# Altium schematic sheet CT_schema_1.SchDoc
size 707 x 532 mm
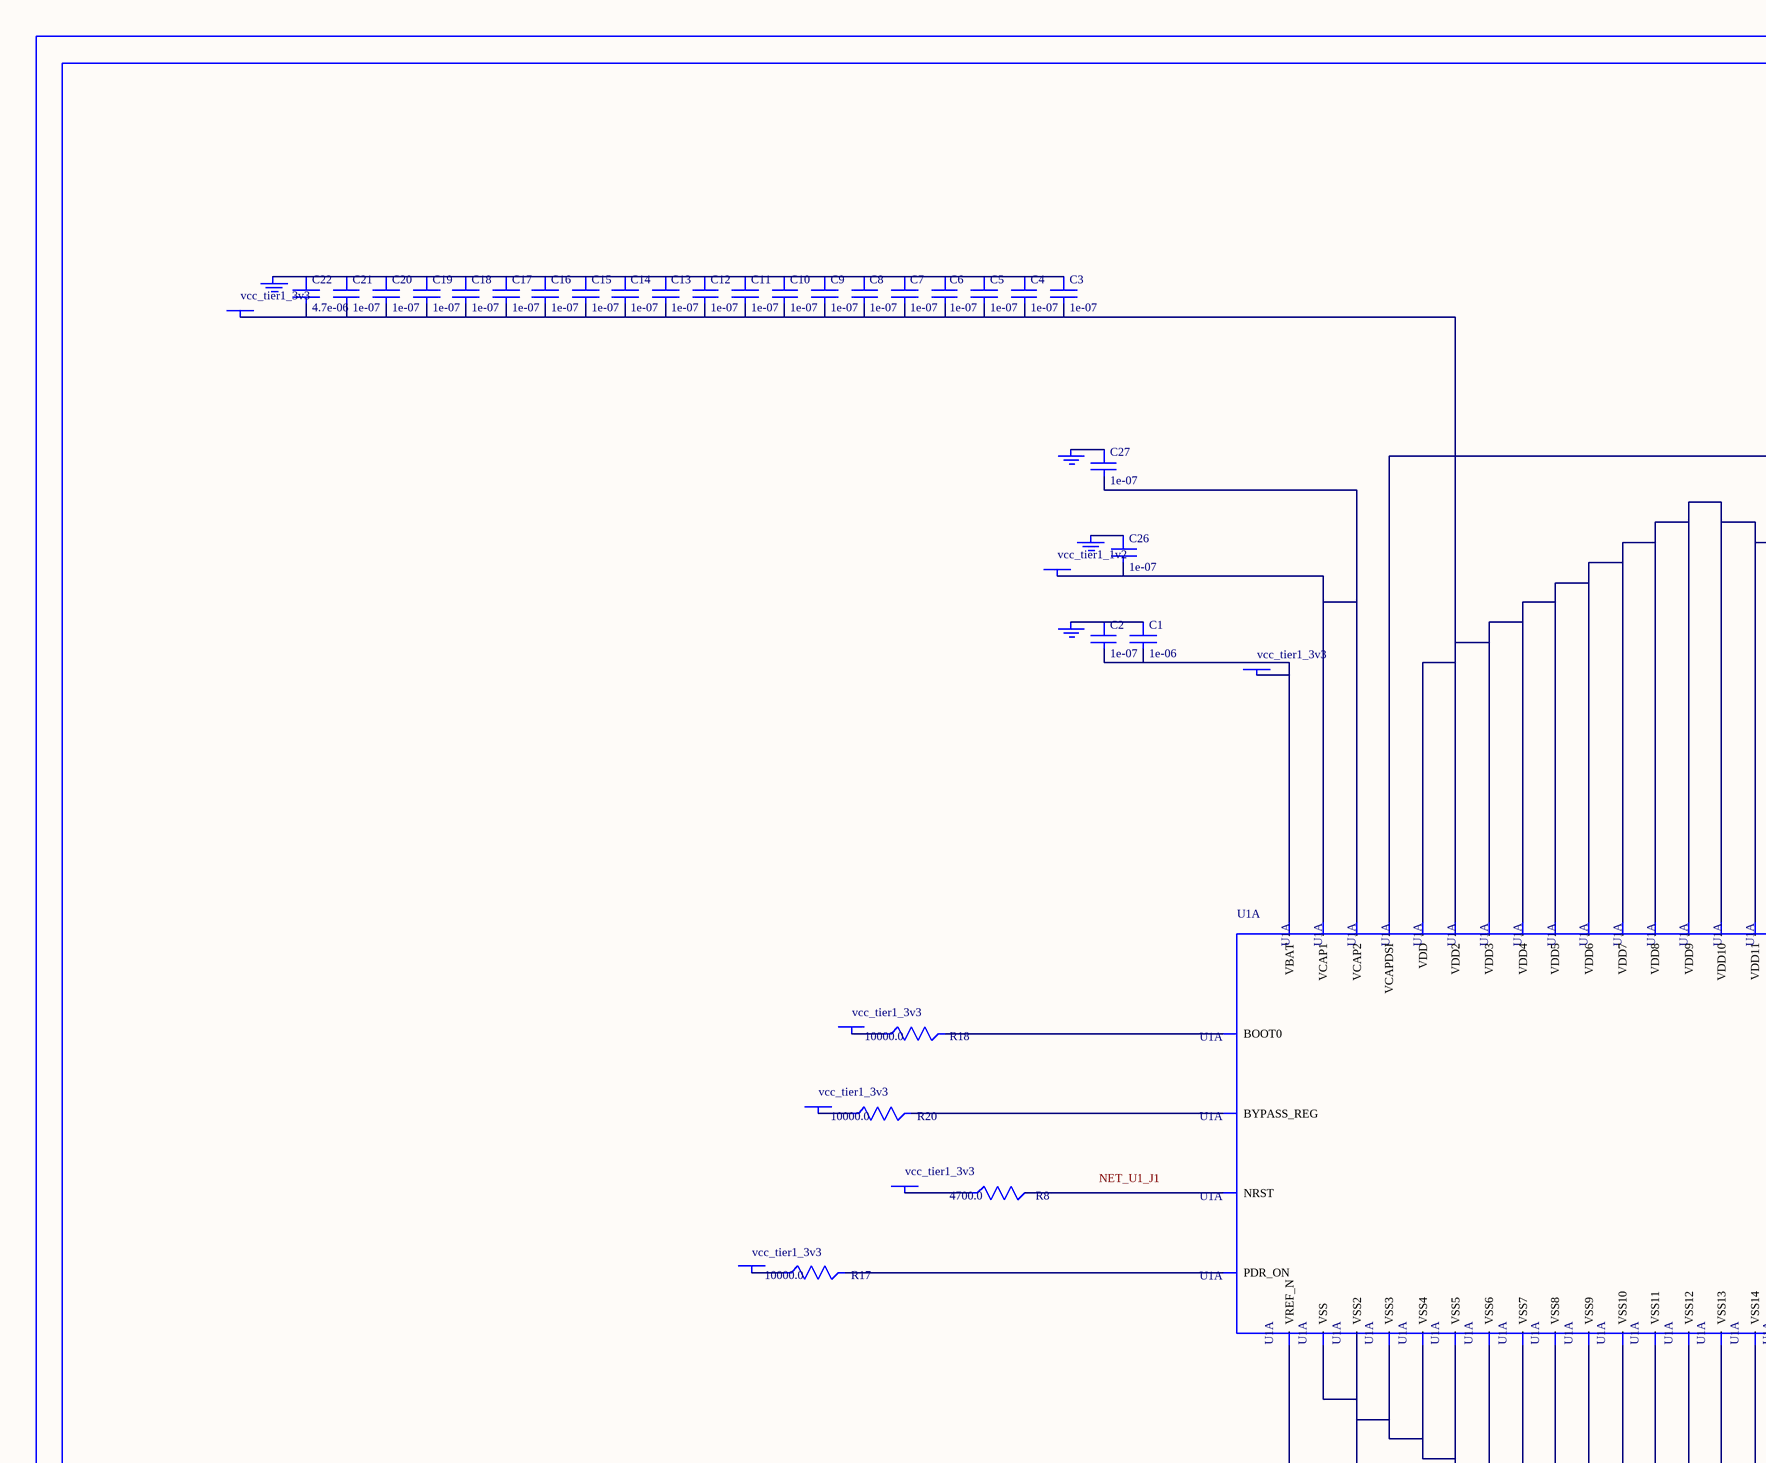
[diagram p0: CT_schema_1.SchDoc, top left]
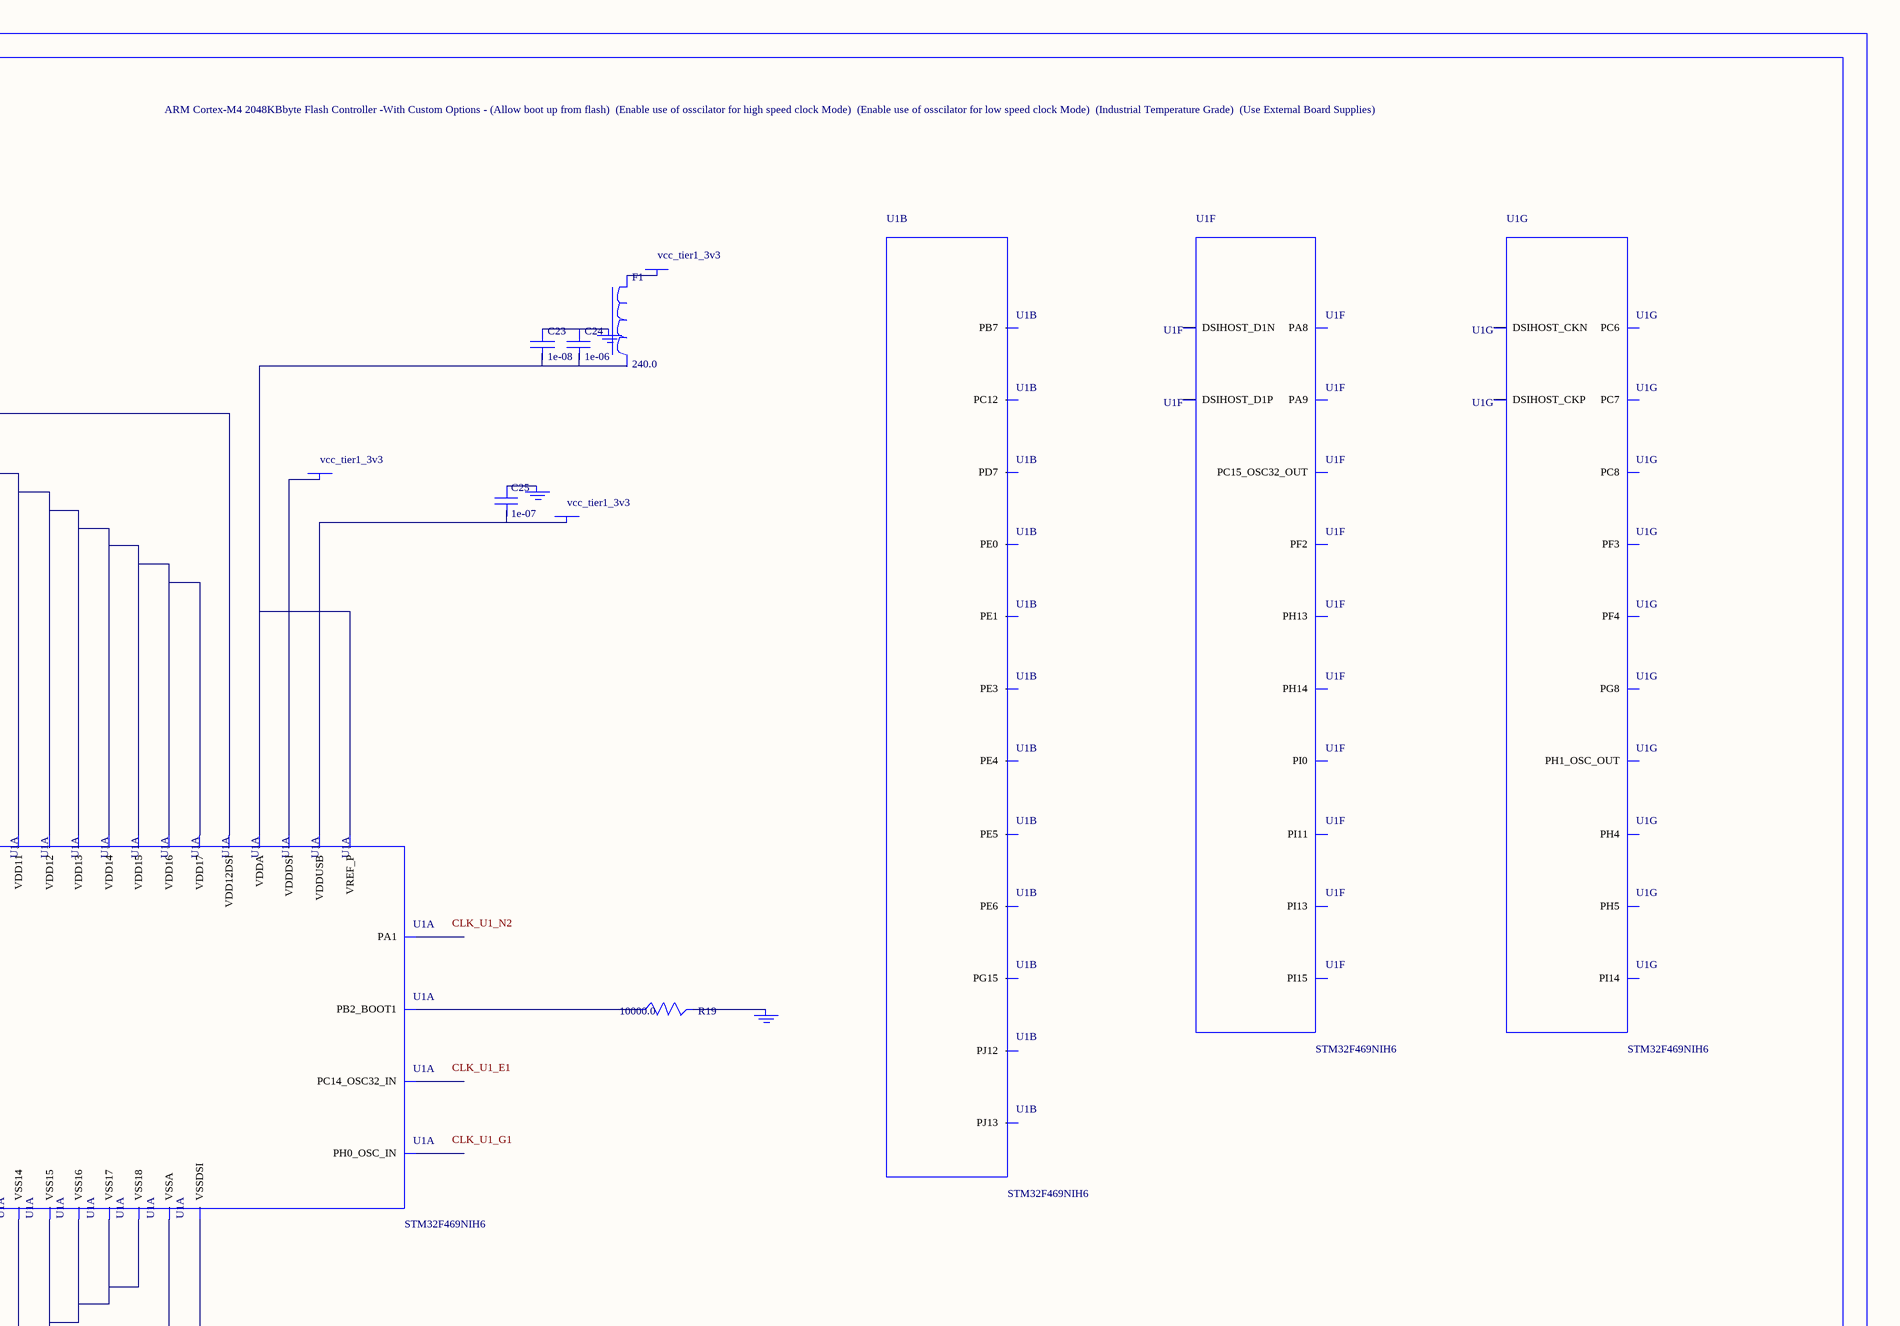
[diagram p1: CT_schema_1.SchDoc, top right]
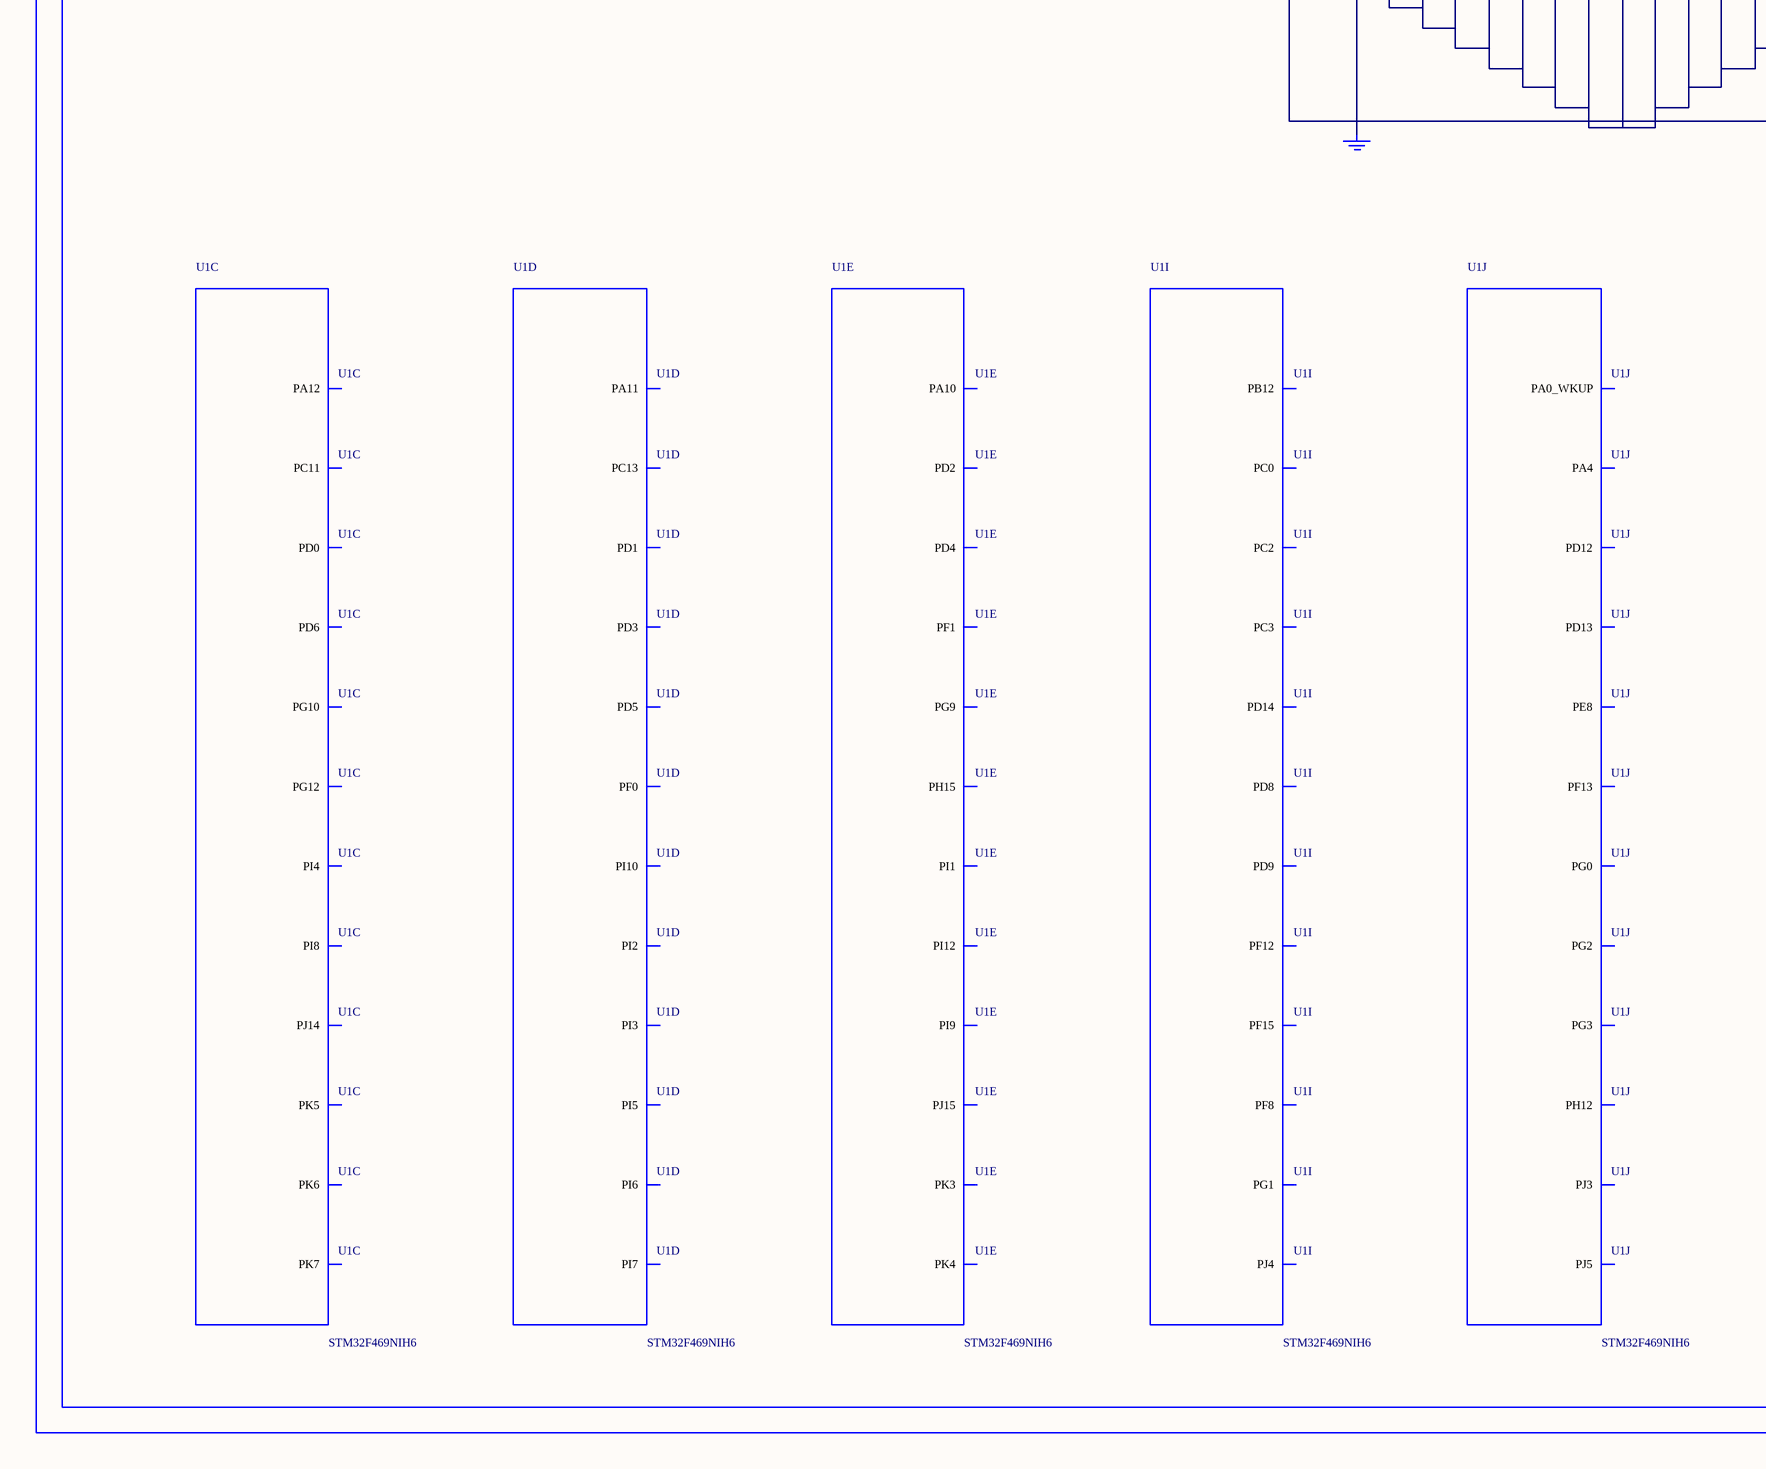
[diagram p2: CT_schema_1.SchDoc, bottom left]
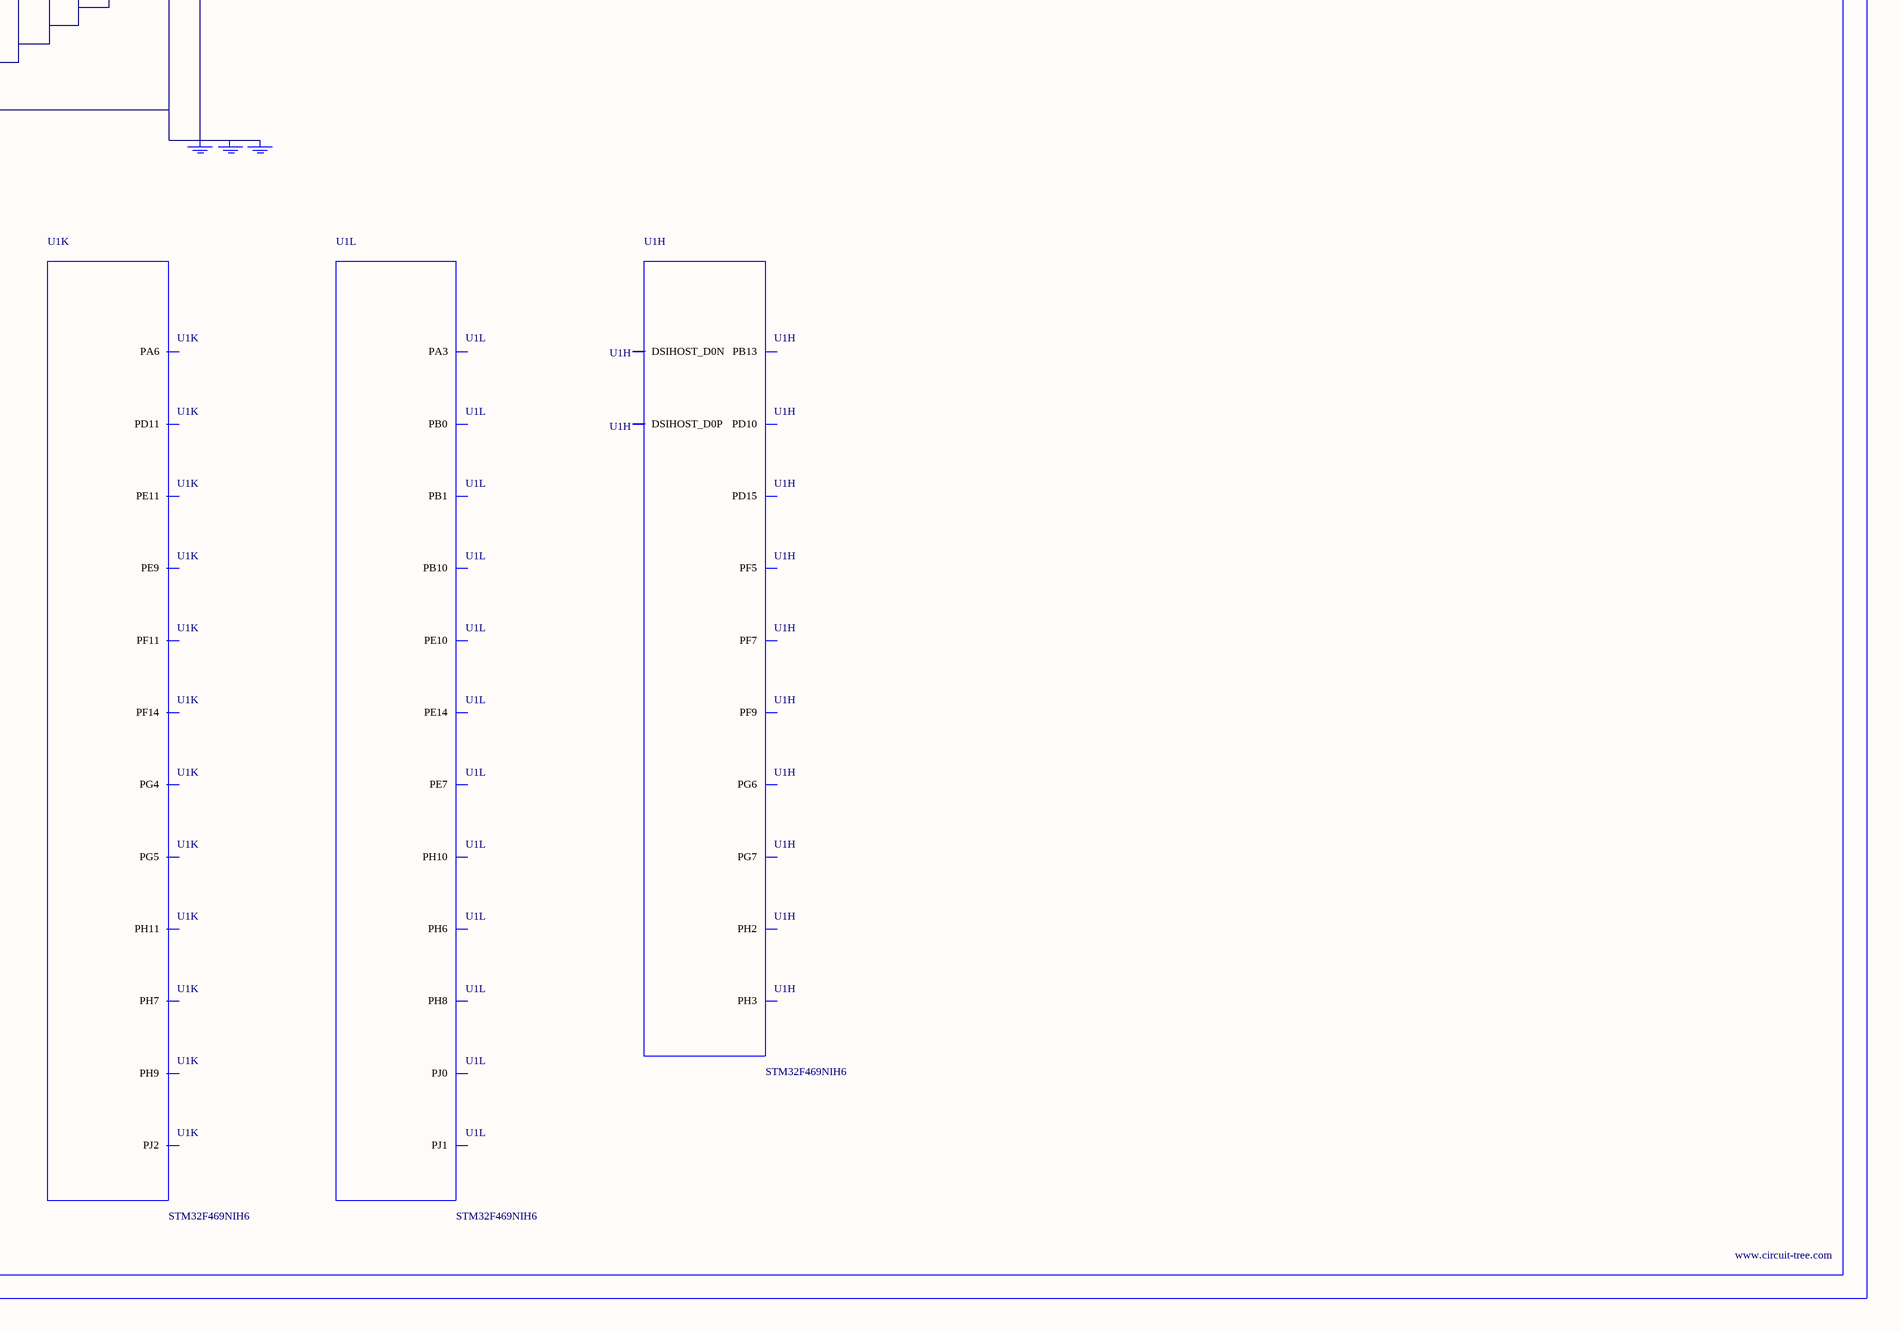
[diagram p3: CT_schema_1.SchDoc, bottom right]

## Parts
BORDER0  (no value)
C1  1e-06  [C0603]
C2  1e-07  [C0603]
C3  1e-07  [C0603]
C4  1e-07  [C0603]
C5  1e-07  [C0603]
C6  1e-07  [C0603]
C7  1e-07  [C0603]
C8  1e-07  [C0603]
C9  1e-07  [C0603]
C10  1e-07  [C0603]
C11  1e-07  [C0603]
C12  1e-07  [C0603]
C13  1e-07  [C0603]
C14  1e-07  [C0603]
C15  1e-07  [C0603]
C16  1e-07  [C0603]
C17  1e-07  [C0603]
C18  1e-07  [C0603]
C19  1e-07  [C0603]
C20  1e-07  [C0603]
C21  1e-07  [C0603]
C22  4.7e-06  [C0603]
C23  1e-08  [C0603]
C24  1e-06  [C0603]
C25  1e-07  [C0603]
C26  1e-07  [C0603]
C27  1e-07  [C0603]
F1  240.0  [L0603]
GND_INSTANCE_0_0  (no value)
GND_INSTANCE_0_1  (no value)
GND_INSTANCE_0_2  (no value)
GND_INSTANCE_0_3  (no value)
GND_INSTANCE_0_4  (no value)
GND_INSTANCE_0_5  (no value)
GND_INSTANCE_0_6  (no value)
GND_INSTANCE_0_7  (no value)
GND_INSTANCE_0_8  (no value)
GND_INSTANCE_0_9  (no value)
GND_INSTANCE_0_10  (no value)
POWER_INSTANCE_0_0  vcc_tier1_3v3
POWER_INSTANCE_0_1  vcc_tier1_3v3
POWER_INSTANCE_0_2  vcc_tier1_3v3
POWER_INSTANCE_0_3  vcc_tier1_3v3
POWER_INSTANCE_0_4  vcc_tier1_3v3
POWER_INSTANCE_0_5  vcc_tier1_3v3
POWER_INSTANCE_0_6  vcc_tier1_3v3
POWER_INSTANCE_0_7  vcc_tier1_1v2
POWER_INSTANCE_0_8  vcc_tier1_3v3
POWER_INSTANCE_0_9  vcc_tier1_3v3
R8  4700.0  [R0603]
R17  10000.0  [R0603]
R18  10000.0  [R0603]
R19  10000.0  [R0603]
R20  10000.0  [R0603]
U1  STM32F469NIH6  [TFBGA216]  (parts A,B,C,D,E,F,G,H,I,J,K,L of 17)

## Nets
NetC1_1: C1.1 C2.1 GND_INSTANCE_0_0.0(GND)
NetC1_2: C1.2 C2.2 POWER_INSTANCE_0_0.0(PWR) U1.C1(VBAT)
NetC3_1: C3.1 C4.1 C5.1 C6.1 C7.1 C8.1 C9.1 C10.1 C11.1 C12.1 C13.1 C14.1 C15.1 C16.1 C17.1 C18.1 C19.1 C20.1 C21.1 C22.1 GND_INSTANCE_0_2.0(GND)
NetC3_2: C3.2 C4.2 C5.2 C6.2 C7.2 C8.2 C9.2 C10.2 C11.2 C12.2 C13.2 C14.2 C15.2 C16.2 C17.2 C18.2 C19.2 C20.2 C21.2 C22.2 POWER_INSTANCE_0_2.0(PWR) U1.E7(VDD2) U1.E8(VDD3) U1.E9(VDD4) U1.E10(VDD) U1.F4(VDD6) U1.F5(VDD7) U1.F11(VDD5) U1.G5(VDD8) U1.H5(VDD9) U1.J5(VDD11) U1.J11(VDD10) U1.K5(VDD13) U1.K11(VDD12) U1.L7(VDD15) U1.L8(VDD16) U1.L9(VDD17) U1.L10(VDD14)
NetC23_1: C23.1 C24.1 GND_INSTANCE_0_1.0(GND)
NetC23_2: C23.2 C24.2 U1.P1(VREF_P) U1.R1(VDDA)
NetC25_1: C25.1 GND_INSTANCE_0_3.0(GND)
NetC25_2: C25.2 POWER_INSTANCE_0_4.0(PWR) U1.G11(VDDUSB)
NetC26_1: C26.1 GND_INSTANCE_0_5.0(GND)
NetC26_2: C26.2 C27.2 POWER_INSTANCE_0_7.0(PWR) U1.E11(VCAP2) U1.L11(VCAP1)
NetC27_1: C27.1 GND_INSTANCE_0_6.0(GND)
NetF1_1: F1.1 POWER_INSTANCE_0_1.0(PWR)
NetGND_INSTANCE_0_4_0: GND_INSTANCE_0_4.0(GND) R19.2
NetGND_INSTANCE_0_7_0: GND_INSTANCE_0_7.0(GND) GND_INSTANCE_0_8.0(GND) GND_INSTANCE_0_9.0(GND) U1.G12(VSSDSI) U1.M1(VSSA) U1.N1(VREF_N)
NetGND_INSTANCE_0_10_0: GND_INSTANCE_0_10.0(GND) U1.F2(VSS2) U1.F6(VSS3) U1.F7(VSS4) U1.F8(VSS5) U1.F9(VSS6) U1.F10(VSS) U1.G6(VSS8) U1.G10(VSS7) U1.H6(VSS10) U1.H10(VSS9) U1.J6(VSS12) U1.J10(VSS11) U1.K6(VSS14) U1.K7(VSS15) U1.K8(VSS16) U1.K9(VSS17) U1.K10(VSS13) U1.L6(VSS18)
NetPOWER_INSTANCE_0_3_0: POWER_INSTANCE_0_3.0(PWR) R17.1
NetPOWER_INSTANCE_0_5_0: POWER_INSTANCE_0_5.0(PWR) R18.1
NetPOWER_INSTANCE_0_6_0: POWER_INSTANCE_0_6.0(PWR) R20.1
NetPOWER_INSTANCE_0_8_0: POWER_INSTANCE_0_8.0(PWR) U1.H11(VDDDSI)
NetPOWER_INSTANCE_0_9_0: POWER_INSTANCE_0_9.0(PWR) R8.1
NetR8_2: R8.2 U1.J1(NRST)
NetR17_2: R17.2 U1.E5(PDR_ON)
NetR18_2: R18.2 U1.E6(BOOT0)
NetR19_1: R19.1 U1.M5(PB2_BOOT1)
NetR20_2: R20.2 U1.L5(BYPASS_REG)
NetU1_G13: U1.G13(VDD12DSI) U1.K12(VCAPDSI)

Not connected (* = marked no-connect by the designer): F1 2; U1 A1(PE4) A2(PE3) A5(PE1) A6(PE0) A11(PD7) A12(PC12) B1(PE5) B2(PE6) B5(PB7) B7(PG15) B9(PJ13) B10(PJ12) B11(PD6) B12(PD0) B13(PC11) B15(PA12) C2(PI8) C3(PI4) C4(PK7) C5(PK6) C6(PK5) C7(PG12) C8(PG10) C9(PJ14) C10(PD5) C11(PD3) C12(PD1) C13(PI3) C14(PI2) C15(PA11) D1(PC13) D2(PF0) D3(PI5) D4(PI7) D5(PI10) D6(PI6) D7(PK4) D8(PK3) D9(PG9) D10(PJ15) D11(PD4) D12(PD2) D13(PH15) D14(PI1) D15(PA10) E1(PC14_OSC32_IN) E2(PF1) E3(PI12) E4(PI9) E12(PH13) E13(PH14) E14(PI0) E15(PA9) F1(PC15_OSC32_OUT) F3(PI11) F12(DSIHOST_D1P) F13(DSIHOST_D1N) F15(PA8) G1(PH0_OSC_IN) G2(PF2) G3(PI13) G4(PI15) G14(PC8) G15(PC7) H1(PH1_OSC_OUT) H2(PF3) H3(PI14) H4(PH4) H12(DSIHOST_CKP) H13(DSIHOST_CKN) H14(PG8) H15(PC6) J2(PF4) J3(PH5) J4(PH3) J12(DSIHOST_D0P) J13(DSIHOST_D0N) J14(PG7) J15(PG6) K1(PF7) K3(PF5) K4(PH2) K13(PD15) K14(PB13) K15(PD10) L2(PF9) L3(PF8) L4(PC3) L12(PD14) L13(PB12) L14(PD9) L15(PD8) M2(PC0) M4(PC2) M6(PF12) M7(PG1) M8(PF15) M9(PJ4) M10(PD12) M11(PD13) M12(PG3) M13(PG2) M14(PJ5) M15(PH12) N2(PA1) N3(PA0_WKUP) N4(PA4) N6(PF13) N7(PG0) N8(PJ3) N9(PE8) N10(PD11) N11(PG5) N12(PG4) N13(PH7) N14(PH9) N15(PH11) P3(PA6) P6(PF14) P7(PJ2) P8(PF11) P9(PE9) P10(PE11) P11(PE14) P12(PB10) P13(PH6) P14(PH8) P15(PH10) R2(PA3) R4(PB1) R5(PB0) R6(PJ0) R7(PJ1) R8(PE7) R9(PE10)

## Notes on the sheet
- Labels drawn without touching a wire or pin: CLK_U1_E1, CLK_U1_G1, CLK_U1_N2, NET_U1_J1

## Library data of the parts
BORDER0 = BORDER_PAGE0
C1 C24 = C0603C105K3RACTU
C2-C21 C25-C27 = 06035C104K4Z2A
C22 = GRM188R6YA475KE15D
C23 = 06035C103K4Z2A
F1 = Z0603C241ASMST
GND_INSTANCE_0_0-GND_INSTANCE_0_10 = GND
POWER_INSTANCE_0_0-POWER_INSTANCE_0_9 = PWR
R8 = RC0603JR-074K7L
R17-R20 = RC0603JR-0710KL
